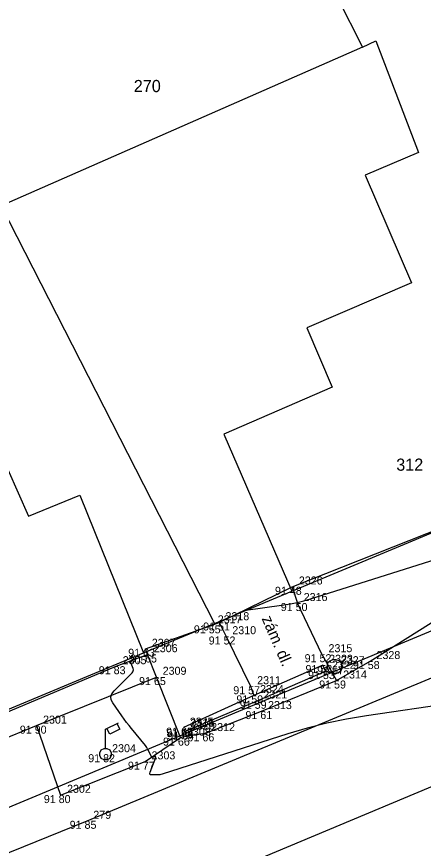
# Model space of a CAD drawing. Extents: x -711081 to -709338, y -1025122 to -1024092.
# Drawn here: x -710619.15 to -710604.9, y -1024867.14 to -1024838.04 of the extents above; entities that cross this region are included whole.
import ezdxf

# ---------------------------------------------------------------- set-up
doc = ezdxf.new("R2010")
doc.units = 0
for name, color, linetype in [('Ex_Minor Contours', 7, 'Continuous'), ('Z_body', 7, 'Continuous'), ('Z_body_cisla', 7, 'Continuous'), ('Z_body_vysky_redukovane', 7, 'Continuous'), ('Z_budova', 7, 'Continuous'), ('Z_katastr_cisla_pozemkova', 7, 'Continuous'), ('Z_katastr_cisla_stavebni', 7, 'Continuous'), ('Z_katastr_hranice', 7, 'Continuous'), ('Z_katastr_hranice_katastralniho_uzemi', 7, 'Continuous'), ('Z_katastr_vnitrni_kresba', 7, 'Continuous'), ('Z_komunikace', 7, 'Continuous'), ('Z_komunikace_osa', 7, 'Continuous'), ('Z_ploty', 7, 'Continuous'), ('Z_popisy', 7, 'Continuous'), ('Z_rozhranni', 7, 'Continuous'), ('Z_site_kanalizace_znaky', 7, 'Continuous'), ('Z_site_vo_znaky', 7, 'Continuous'), ('Z_vstupy', 7, 'Continuous'), ('Z_zlabek', 7, 'Continuous')]:
    doc.layers.add(name, color=color, linetype=linetype)

# ---------------------------------------------------------------- blocks, each defined once
blk = doc.blocks.new('POINT_DISPLAY')
blk.add_line((0, 0), (0, 0))
blk = doc.blocks.new('Z13')
for p, q in [((0, 0.88), (0.45, 1.1)), ((0, 0.2), (0, 0.88)), ((0.15, 0.7), (0.05, 0.9)), ((0.5, 0.88), (0.15, 0.7)), ((0.4, 1.07), (0.5, 0.88)), ((-0.2, 0.05), (-0.15, 0.15)), ((-0.2, -0.05), (-0.2, 0.05)), ((-0.15, 0.15), (-0.05, 0.2)), ((-0.05, 0.2), (0.05, 0.2)), ((0.05, 0.2), (0.15, 0.15)), ((0.15, 0.15), (0.2, 0.05)), ((0.2, 0.05), (0.2, -0.05)), ((-0.15, -0.15), (-0.2, -0.05)), ((-0.05, -0.2), (-0.15, -0.15)), ((0.05, -0.2), (-0.05, -0.2)), ((0.15, -0.15), (0.05, -0.2)), ((0.2, -0.05), (0.15, -0.15))]:
    blk.add_line(p, q)
blk = doc.blocks.new('Z620')
for p, q in [((-0.25, 0.05), (-0.23, 0.13)), ((-0.25, -0.05), (-0.25, 0.05)), ((-0.23, 0.13), (-0.17, 0.2)), ((-0.17, 0.2), (-0.05, 0.25)), ((-0.05, 0.25), (0.05, 0.25)), ((0.05, 0.25), (0.17, 0.2)), ((0.17, 0.2), (0.23, 0.13)), ((0.23, 0.13), (0.25, 0.05)), ((0.25, 0.05), (0.25, -0.05)), ((-0.2, -0.17), (-0.25, -0.05)), ((-0.13, -0.23), (-0.2, -0.17)), ((-0.05, -0.25), (-0.13, -0.23)), ((0.05, -0.25), (-0.05, -0.25)), ((0.13, -0.23), (0.05, -0.25)), ((0.2, -0.17), (0.13, -0.23)), ((0.25, -0.05), (0.2, -0.17))]:
    blk.add_line(p, q)

msp = doc.modelspace()

# ---------------------------------------------------------------- linework, layer by layer
at = {"layer": 'Ex_Minor Contours'}
for points in [[(-710611.197, -1024858.823), (-710609.782, -1024858.626), (-710609.547, -1024858.588), (-710609.314, -1024858.541), (-710609.084, -1024858.484), (-710608.856, -1024858.417), (-710604.005, -1024856.886)], [(-710603.867, -1024862.064), (-710606.893, -1024862.502), (-710607.592, -1024862.618), (-710608.285, -1024862.763), (-710608.972, -1024862.937), (-710609.651, -1024863.14), (-710614.046, -1024864.552), (-710614.09, -1024864.564), (-710614.135, -1024864.572), (-710614.181, -1024864.577), (-710614.227, -1024864.577), (-710614.413, -1024864.572), (-710614.452, -1024864.566), (-710614.475, -1024864.548), (-710614.482, -1024864.521), (-710614.473, -1024864.483), (-710614.274, -1024863.967), (-710614.27, -1024863.951), (-710614.273, -1024863.941), (-710614.283, -1024863.936), (-710614.299, -1024863.937), (-710614.377, -1024863.95), (-710614.395, -1024863.951), (-710614.411, -1024863.947), (-710614.423, -1024863.937), (-710614.433, -1024863.921), (-710614.535, -1024863.702), (-710614.556, -1024863.66), (-710614.58, -1024863.62), (-710614.606, -1024863.581), (-710614.635, -1024863.544), (-710615.121, -1024862.952), (-710615.208, -1024862.844), (-710615.293, -1024862.735), (-710615.375, -1024862.624), (-710615.455, -1024862.511), (-710615.772, -1024862.057), (-710615.829, -1024861.946), (-710615.841, -1024861.838), (-710615.81, -1024861.734), (-710615.734, -1024861.635), (-710615.1, -1024861.005), (-710615.073, -1024860.971), (-710615.059, -1024860.934), (-710615.057, -1024860.894), (-710615.068, -1024860.851), (-710615.171, -1024860.588)]]:
    msp.add_lwpolyline(points, dxfattribs=at)
at = {"layer": 'Z_budova'}
for p, q in [((-710609.49, -1024857.99), (-710604.21, -1024855.9)), ((-710614.56, -1024860.36), (-710614.63, -1024860.16)), ((-710615.66, -1024860.77), (-710614.56, -1024860.36)), ((-710623.67, -1024864.13), (-710615.66, -1024860.77))]:
    msp.add_line(p, q, dxfattribs=at)
at = {"layer": 'Z_katastr_hranice'}
for p, q in [((-710609.16, -1024834.84), (-710607.03, -1024839.11)), ((-710607.03, -1024839.11), (-710619.69, -1024844.66)), ((-710619.69, -1024844.66), (-710612.22, -1024859.27)), ((-710609.5, -1024858.14), (-710597.39, -1024853.09)), ((-710612.22, -1024859.27), (-710609.5, -1024858.14)), ((-710614.7, -1024860.3), (-710612.22, -1024859.27)), ((-710623.8, -1024864.09), (-710614.7, -1024860.3))]:
    msp.add_line(p, q, dxfattribs=at)
at = {"layer": 'Z_katastr_hranice_katastralniho_uzemi'}
msp.add_line((-710587.89, -1024852.54), (-710688.39, -1024894.53), dxfattribs=at)
msp.add_line((-710587.89, -1024852.54), (-710688.39, -1024894.53), dxfattribs=at)
at = {"layer": 'Z_katastr_vnitrni_kresba'}
for p, q in [((-710607.03, -1024839.11), (-710606.56, -1024838.88)), ((-710606.56, -1024838.88), (-710605.07, -1024842.79)), ((-710605.07, -1024842.79), (-710606.94, -1024843.59)), ((-710606.94, -1024843.59), (-710605.31, -1024847.35)), ((-710605.31, -1024847.35), (-710608.98, -1024848.93)), ((-710608.98, -1024848.93), (-710608.09, -1024851.01)), ((-710608.09, -1024851.01), (-710611.89, -1024852.65)), ((-710620.41, -1024851.74), (-710618.73, -1024855.52)), ((-710611.89, -1024852.65), (-710609.5, -1024858.14)), ((-710618.73, -1024855.52), (-710616.93, -1024854.79)), ((-710616.93, -1024854.79), (-710614.7, -1024860.3))]:
    msp.add_line(p, q, dxfattribs=at)
at = {"layer": 'Z_komunikace'}
for p, q in [((-710616.68, -1024866.18), (-710603.27, -1024860.62)), ((-710629.53, -1024871.41), (-710616.68, -1024866.18))]:
    msp.add_line(p, q, dxfattribs=at)
at = {"layer": 'Z_komunikace_osa'}
msp.add_line((-710615.69, -1024869.61), (-710601.78, -1024863.8), dxfattribs=at)
at = {"layer": 'Z_ploty'}
msp.add_line((-710612.33, -1024859.34), (-710612.05, -1024859.24), dxfattribs=at)
at = {"layer": 'Z_rozhranni'}
for p, q in [((-710609.49, -1024857.99), (-710609.31, -1024858.56)), ((-710606.76, -1024860.59), (-710603.34, -1024858.44)), ((-710608.45, -1024860.35), (-710609.31, -1024858.56)), ((-710612.05, -1024859.24), (-710611.81, -1024859.73)), ((-710611.81, -1024859.73), (-710610.95, -1024861.47)), ((-710614.25, -1024861.15), (-710614.56, -1024860.36)), ((-710608.45, -1024860.35), (-710607.94, -1024861.27)), ((-710607.94, -1024861.27), (-710606.76, -1024860.59)), ((-710618.45, -1024862.85), (-710614.25, -1024861.15)), ((-710613.41, -1024863.27), (-710614.25, -1024861.15)), ((-710610.57, -1024862.34), (-710607.94, -1024861.27)), ((-710610.95, -1024861.47), (-710610.84, -1024861.79)), ((-710612.55, -1024863.12), (-710610.57, -1024862.34)), ((-710621.57, -1024864.1), (-710618.45, -1024862.85)), ((-710618.45, -1024862.85), (-710617.61, -1024865.28)), ((-710612.55, -1024863.12), (-710613.41, -1024863.27)), ((-710614.64, -1024864.11), (-710613.41, -1024863.27)), ((-710617.61, -1024865.28), (-710614.64, -1024864.11))]:
    msp.add_line(p, q, dxfattribs=at)
at = {"layer": 'Z_vstupy'}
for p, q in [((-710612.05, -1024859.24), (-710609.49, -1024857.99)), ((-710614.63, -1024860.16), (-710612.33, -1024859.34))]:
    msp.add_line(p, q, dxfattribs=at)
at = {"layer": 'Z_zlabek'}
for p, q in [((-710608.42, -1024860.73), (-710610.84, -1024861.79)), ((-710608.33, -1024860.94), (-710608.42, -1024860.73)), ((-710610.72, -1024861.98), (-710608.33, -1024860.94)), ((-710610.84, -1024861.79), (-710613.3, -1024862.92)), ((-710613.26, -1024863.06), (-710610.72, -1024861.98)), ((-710613.29, -1024862.97), (-710613.26, -1024863.06))]:
    msp.add_line(p, q, dxfattribs=at)

# ---------------------------------------------------------------- block references
at = {"layer": 'Z_body'}
for p in [(-710609.49, -1024857.99), (-710609.31, -1024858.56), (-710612.33, -1024859.34), (-710612.05, -1024859.24), (-710611.81, -1024859.73), (-710614.63, -1024860.16), (-710614.56, -1024860.36), (-710608.45, -1024860.35), (-710615.66, -1024860.77), (-710608.42, -1024860.73), (-710608.01, -1024860.78), (-710606.76, -1024860.59), (-710608.33, -1024860.94), (-710614.25, -1024861.15), (-710607.94, -1024861.27), (-710610.95, -1024861.47), (-710610.84, -1024861.79), (-710610.72, -1024861.98), (-710610.57, -1024862.34), (-710618.45, -1024862.85), (-710613.3, -1024862.92), (-710613.29, -1024862.97), (-710613.26, -1024863.06), (-710612.55, -1024863.12), (-710613.41, -1024863.27), (-710616.03, -1024863.85), (-710614.64, -1024864.11), (-710617.61, -1024865.28), (-710616.68, -1024866.18)]:
    msp.add_blockref('POINT_DISPLAY', p, dxfattribs=at)
at = {"layer": 'Z_site_kanalizace_znaky'}
msp.add_blockref('Z620', (-710608.01, -1024860.78), dxfattribs=at)
at = {"layer": 'Z_site_vo_znaky'}
msp.add_blockref('Z13', (-710616.03, -1024863.85), dxfattribs=at)

# ---------------------------------------------------------------- texts
at = {"layer": 'Z_body_cisla'}
for s, p in [('2326', (-710609.26, -1024857.91)), ('2316', (-710609.09, -1024858.49)), ('2317', (-710612.1, -1024859.27)), ('2318', (-710611.83, -1024859.16)), ('2310', (-710611.59, -1024859.65)), ('2307', (-710614.41, -1024860.09)), ('2306', (-710614.34, -1024860.28)), ('2315', (-710608.22, -1024860.28)), ('2305', (-710615.43, -1024860.7)), ('2323', (-710608.2, -1024860.65)), ('2327', (-710607.79, -1024860.7)), ('2328', (-710606.54, -1024860.52)), ('2309', (-710614.03, -1024861.07)), ('2322', (-710608.1, -1024860.86)), ('2314', (-710607.71, -1024861.2)), ('2311', (-710610.72, -1024861.4)), ('2324', (-710610.62, -1024861.71)), ('2321', (-710610.5, -1024861.9)), ('2313', (-710610.34, -1024862.27)), ('2301', (-710618.22, -1024862.78)), ('2325', (-710613.08, -1024862.85)), ('2319', (-710613.06, -1024862.9)), ('2320', (-710613.04, -1024862.99)), ('2312', (-710612.33, -1024863.04)), ('2308', (-710613.18, -1024863.2)), ('2304', (-710615.8, -1024863.78)), ('2303', (-710614.42, -1024864.03)), ('2302', (-710617.38, -1024865.2)), ('279', (-710616.46, -1024866.11))]:
    msp.add_text(s, height=0.28, dxfattribs=at).set_placement(p)
at = {"layer": 'Z_body_vysky_redukovane'}
for s, p in [('91 48', (-710610.097, -1024858.27)), ('91 50', (-710609.893, -1024858.84)), ('91 55', (-710612.937, -1024859.62)), ('91 51', (-710612.61, -1024859.52)), ('91 52', (-710612.417, -1024860.01)), ('91 63', (-710615.237, -1024860.44)), ('91 65', (-710615.167, -1024860.64)), ('91 52', (-710609.057, -1024860.63)), ('91 83', (-710616.267, -1024861.05)), ('91 53', (-710609.027, -1024861.01)), ('91 57', (-710608.617, -1024861.06)), ('91 58', (-710607.367, -1024860.87)), ('91 53', (-710608.937, -1024861.22)), ('91 65', (-710614.857, -1024861.43)), ('91 59', (-710608.547, -1024861.55)), ('91 57', (-710611.557, -1024861.75)), ('91 59', (-710611.447, -1024862.07)), ('91 59', (-710611.327, -1024862.26)), ('91 61', (-710611.13, -1024862.62)), ('91 90', (-710619.033, -1024863.13)), ('91 65', (-710613.907, -1024863.2)), ('91 64', (-710613.897, -1024863.25)), ('91 64', (-710613.867, -1024863.34)), ('91 66', (-710613.157, -1024863.4)), ('91 66', (-710614.017, -1024863.55)), ('91 82', (-710616.637, -1024864.13)), ('91 77', (-710615.247, -1024864.39)), ('91 80', (-710618.193, -1024865.56)), ('91 85', (-710617.287, -1024866.46))]:
    msp.add_text(s, height=0.28, dxfattribs=at).set_placement(p)
at = {"layer": 'Z_katastr_cisla_pozemkova'}
msp.add_text('270', height=0.425, dxfattribs=at).set_placement((-710615.043, -1024840.679))
at = {"layer": 'Z_katastr_cisla_stavebni'}
msp.add_text('312', height=0.425, dxfattribs=at).set_placement((-710605.849, -1024853.929))
at = {"layer": 'Z_popisy'}
msp.add_text('zám. dl.', height=0.4, rotation=293.4, dxfattribs=at).set_placement((-710610.57, -1024859.1))

doc.saveas('drawing.dxf')
